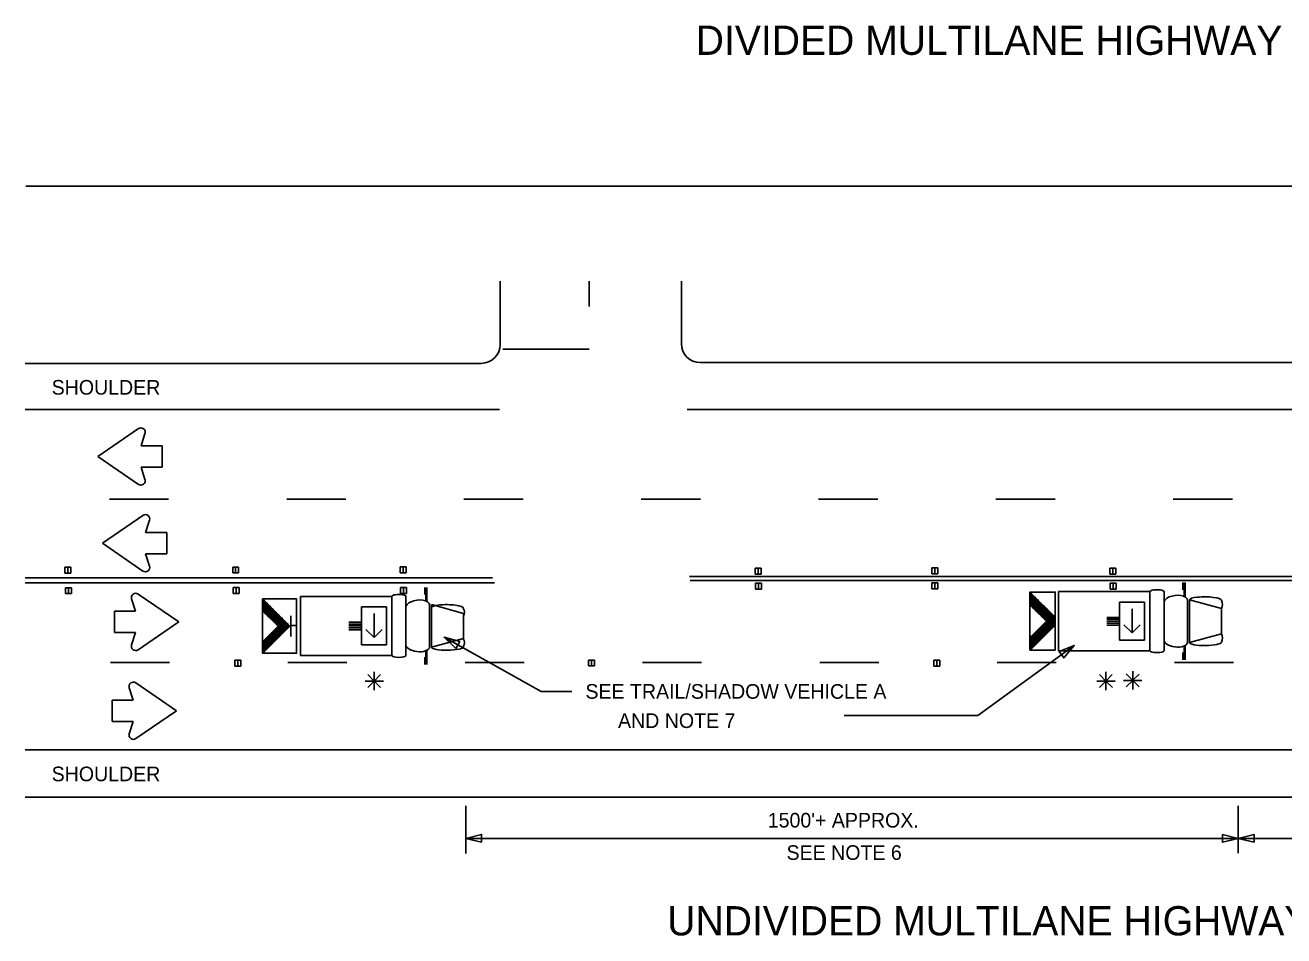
# Model space of a CAD drawing. Extents: x 1373848 to 1374003, y 380642 to 381248.
# Drawn here: x 1373848.1 to 1373899.8, y 380980.5 to 381017.9 of the extents above; entities that cross this region are included whole.
import ezdxf

# ---------------------------------------------------------------- set-up
doc = ezdxf.new("R2010")
doc.units = 0
doc.layers.add('Level 1', color=7, linetype='Continuous')
doc.layers.add('Working Level 1', color=7, linetype='Continuous')

msp = doc.modelspace()

# ---------------------------------------------------------------- linework, layer by layer
at = {"layer": 'Level 1'}
for points in [[(1373865.303, 380992.763), (1373869.287, 380990.533), (1373870.541, 380990.533)], [(1373891.159, 380992.429), (1373887.203, 380989.558), (1373881.714, 380989.558)]]:
    msp.add_lwpolyline(points, dxfattribs=at)
at = {"layer": 'Working Level 1'}
for p, q in [((1373848.144, 381011.273), (1373928.089, 381011.273)), ((1373867.608, 381004.776), (1373867.608, 381007.375)), ((1373875.04, 381004.805), (1373875.04, 381007.375)), ((1373867.714, 381004.589), (1373871.261, 381004.589)), ((1373848.118, 381004), (1373866.832, 381004)), ((1373875.816, 381004.029), (1373928.123, 381004.029)), ((1373848.118, 381002.105), (1373867.574, 381002.105)), ((1373875.274, 381002.105), (1373928.123, 381002.105)), ((1373851.099, 381000.18), (1373852.766, 381001.324)), ((1373852.871, 381000.616), (1373853.034, 381001.124)), ((1373851.099, 381000.18), (1373852.766, 380999.036)), ((1373853.738, 381000.616), (1373852.871, 381000.616)), ((1373853.738, 381000.616), (1373853.738, 380999.743)), ((1373853.738, 380999.743), (1373852.871, 380999.743)), ((1373852.871, 380999.743), (1373853.034, 380999.236)), ((1373851.285, 380996.622), (1373852.952, 380997.765)), ((1373853.057, 380997.058), (1373853.22, 380997.566)), ((1373851.285, 380996.622), (1373852.952, 380995.478)), ((1373853.925, 380997.058), (1373853.057, 380997.058)), ((1373853.925, 380997.058), (1373853.925, 380996.185)), ((1373853.925, 380996.185), (1373853.057, 380996.185)), ((1373853.057, 380996.185), (1373853.22, 380995.678)), ((1373849.752, 380995.633), (1373849.751, 380995.39)), ((1373849.994, 380995.633), (1373849.752, 380995.633)), ((1373849.873, 380995.633), (1373849.873, 380995.39)), ((1373849.994, 380995.39), (1373849.994, 380995.633)), ((1373856.875, 380995.644), (1373856.632, 380995.644)), ((1373856.632, 380995.644), (1373856.632, 380995.401)), ((1373856.754, 380995.644), (1373856.754, 380995.401)), ((1373856.875, 380995.401), (1373856.875, 380995.644)), ((1373863.507, 380995.656), (1373863.506, 380995.413)), ((1373863.749, 380995.656), (1373863.507, 380995.656)), ((1373863.628, 380995.656), (1373863.628, 380995.413)), ((1373863.749, 380995.413), (1373863.749, 380995.656)), ((1373878.314, 380995.591), (1373878.071, 380995.591)), ((1373878.071, 380995.591), (1373878.071, 380995.348)), ((1373878.193, 380995.591), (1373878.193, 380995.348)), ((1373878.314, 380995.348), (1373878.314, 380995.591)), ((1373885.558, 380995.609), (1373885.315, 380995.609)), ((1373885.315, 380995.609), (1373885.315, 380995.366)), ((1373885.437, 380995.609), (1373885.437, 380995.366)), ((1373885.558, 380995.366), (1373885.558, 380995.609)), ((1373892.625, 380995.601), (1373892.624, 380995.358)), ((1373892.867, 380995.601), (1373892.625, 380995.601)), ((1373892.746, 380995.601), (1373892.746, 380995.358)), ((1373892.867, 380995.358), (1373892.867, 380995.601)), ((1373848.118, 380995.204), (1373867.298, 380995.204)), ((1373849.751, 380995.39), (1373849.994, 380995.39)), ((1373856.632, 380995.401), (1373856.875, 380995.401)), ((1373863.506, 380995.413), (1373863.749, 380995.413)), ((1373875.372, 380995.257), (1373928.123, 380995.257)), ((1373875.406, 380995.089), (1373928.123, 380995.089)), ((1373878.071, 380995.348), (1373878.314, 380995.348)), ((1373885.315, 380995.366), (1373885.558, 380995.366)), ((1373892.624, 380995.358), (1373892.867, 380995.358)), ((1373895.619, 380994.707), (1373895.619, 380995.004)), ((1373895.666, 380994.422), (1373895.666, 380995.004)), ((1373895.706, 380994.422), (1373895.706, 380995.004)), ((1373848.118, 380994.992), (1373867.378, 380994.992)), ((1373850.015, 380994.797), (1373849.772, 380994.797)), ((1373849.772, 380994.797), (1373849.772, 380994.554)), ((1373849.772, 380994.554), (1373850.015, 380994.554)), ((1373849.894, 380994.797), (1373849.893, 380994.554)), ((1373850.015, 380994.554), (1373850.015, 380994.797)), ((1373854.418, 380993.394), (1373852.751, 380994.537)), ((1373856.653, 380994.808), (1373856.652, 380994.565)), ((1373856.652, 380994.565), (1373856.895, 380994.565)), ((1373856.895, 380994.808), (1373856.653, 380994.808)), ((1373856.774, 380994.808), (1373856.774, 380994.565)), ((1373856.895, 380994.565), (1373856.895, 380994.808)), ((1373863.515, 380994.808), (1373863.514, 380994.565)), ((1373863.514, 380994.565), (1373863.757, 380994.565)), ((1373863.757, 380994.808), (1373863.515, 380994.808)), ((1373863.636, 380994.808), (1373863.636, 380994.565)), ((1373863.757, 380994.565), (1373863.757, 380994.808)), ((1373864.515, 380994.514), (1373864.515, 380994.811)), ((1373864.562, 380994.229), (1373864.562, 380994.811)), ((1373864.601, 380994.229), (1373864.601, 380994.811)), ((1373878.325, 380994.98), (1373878.082, 380994.98)), ((1373878.082, 380994.98), (1373878.082, 380994.737)), ((1373878.082, 380994.737), (1373878.325, 380994.737)), ((1373878.204, 380994.98), (1373878.204, 380994.737)), ((1373878.325, 380994.737), (1373878.325, 380994.98)), ((1373885.561, 380994.991), (1373885.318, 380994.991)), ((1373885.318, 380994.991), (1373885.318, 380994.748)), ((1373885.318, 380994.748), (1373885.561, 380994.748)), ((1373885.44, 380994.991), (1373885.439, 380994.748)), ((1373885.561, 380994.748), (1373885.561, 380994.991)), ((1373889.343, 380994.617), (1373890.379, 380993.582)), ((1373890.514, 380994.635), (1373894.268, 380994.635)), ((1373890.514, 380992.209), (1373890.514, 380994.635)), ((1373892.878, 380994.984), (1373892.635, 380994.984)), ((1373892.635, 380994.984), (1373892.635, 380994.741)), ((1373892.635, 380994.741), (1373892.878, 380994.741)), ((1373892.757, 380994.984), (1373892.757, 380994.741)), ((1373892.878, 380994.741), (1373892.878, 380994.984)), ((1373894.268, 380993.422), (1373894.268, 380994.635)), ((1373894.844, 380993.422), (1373894.844, 380994.635)), ((1373852.646, 380993.83), (1373852.483, 380994.337)), ((1373857.861, 380994.338), (1373858.98, 380993.221)), ((1373859.409, 380994.442), (1373863.164, 380994.442)), ((1373859.409, 380992.016), (1373859.409, 380994.442)), ((1373862.944, 380994.005), (1373861.917, 380994.005)), ((1373861.917, 380992.453), (1373861.917, 380994.005)), ((1373862.944, 380994.005), (1373862.944, 380992.453)), ((1373863.164, 380993.229), (1373863.164, 380994.442)), ((1373863.739, 380993.229), (1373863.739, 380994.442)), ((1373864.703, 380993.229), (1373864.703, 380994.103)), ((1373864.783, 380994.103), (1373866.096, 380993.744)), ((1373864.783, 380993.229), (1373864.783, 380994.103)), ((1373889.343, 380994.099), (1373890.027, 380993.419)), ((1373894.048, 380994.198), (1373893.022, 380994.198)), ((1373893.022, 380992.646), (1373893.022, 380994.198)), ((1373894.048, 380994.198), (1373894.048, 380992.646)), ((1373895.807, 380993.422), (1373895.807, 380994.296)), ((1373895.887, 380994.296), (1373897.2, 380993.937)), ((1373895.887, 380993.422), (1373895.887, 380994.296)), ((1373851.778, 380992.957), (1373851.778, 380993.83)), ((1373851.778, 380993.83), (1373852.646, 380993.83)), ((1373857.861, 380993.853), (1373858.503, 380993.214)), ((1373859.017, 380992.8), (1373859.017, 380993.641)), ((1373862.431, 380993.742), (1373862.431, 380992.748)), ((1373866.096, 380993.229), (1373866.096, 380993.744)), ((1373893.022, 380993.577), (1373892.499, 380993.577)), ((1373893.022, 380993.499), (1373892.499, 380993.499)), ((1373893.535, 380993.935), (1373893.535, 380992.941)), ((1373897.2, 380993.422), (1373897.2, 380993.937)), ((1373851.778, 380992.957), (1373852.646, 380992.957)), ((1373852.646, 380992.957), (1373852.483, 380992.45)), ((1373854.418, 380993.394), (1373852.751, 380992.25)), ((1373857.861, 380992.575), (1373858.503, 380993.214)), ((1373857.868, 380992.108), (1373858.98, 380993.221)), ((1373859.251, 380993.241), (1373859.01, 380993.241)), ((1373861.917, 380993.384), (1373861.395, 380993.384)), ((1373861.917, 380993.306), (1373861.395, 380993.306)), ((1373861.917, 380993.229), (1373861.395, 380993.229)), ((1373861.917, 380993.151), (1373861.395, 380993.151)), ((1373861.917, 380993.073), (1373861.395, 380993.073)), ((1373862.431, 380992.748), (1373862.093, 380993.086)), ((1373862.431, 380992.748), (1373862.76, 380993.078)), ((1373863.164, 380993.229), (1373863.164, 380992.017)), ((1373863.739, 380993.229), (1373863.739, 380992.017)), ((1373864.703, 380993.229), (1373864.703, 380992.356)), ((1373864.783, 380993.229), (1373864.783, 380992.356)), ((1373866.096, 380993.229), (1373866.096, 380992.714)), ((1373889.343, 380992.736), (1373890.027, 380993.419)), ((1373889.35, 380992.239), (1373890.374, 380993.264)), ((1373893.022, 380993.422), (1373892.499, 380993.422)), ((1373893.022, 380993.344), (1373892.499, 380993.344)), ((1373893.022, 380993.266), (1373892.499, 380993.266)), ((1373893.535, 380992.941), (1373893.197, 380993.279)), ((1373893.535, 380992.941), (1373893.864, 380993.271)), ((1373894.268, 380993.422), (1373894.268, 380992.21)), ((1373894.844, 380993.422), (1373894.844, 380992.21)), ((1373895.807, 380993.422), (1373895.807, 380992.549)), ((1373895.887, 380993.422), (1373895.887, 380992.549)), ((1373897.2, 380993.422), (1373897.2, 380992.908)), ((1373862.944, 380992.453), (1373861.917, 380992.453)), ((1373864.783, 380992.356), (1373866.096, 380992.714)), ((1373894.048, 380992.646), (1373893.022, 380992.646)), ((1373895.666, 380992.423), (1373895.666, 380991.84)), ((1373895.706, 380992.423), (1373895.706, 380991.84)), ((1373895.887, 380992.549), (1373897.2, 380992.908)), ((1373859.409, 380992.017), (1373863.164, 380992.017)), ((1373864.515, 380991.944), (1373864.515, 380991.647)), ((1373864.562, 380992.229), (1373864.562, 380991.647)), ((1373864.601, 380992.229), (1373864.601, 380991.647)), ((1373890.514, 380992.21), (1373894.268, 380992.21)), ((1373895.619, 380992.137), (1373895.619, 380991.84)), ((1373856.963, 380991.818), (1373856.72, 380991.818)), ((1373856.72, 380991.818), (1373856.72, 380991.575)), ((1373856.72, 380991.575), (1373856.963, 380991.575)), ((1373856.842, 380991.818), (1373856.841, 380991.575)), ((1373856.963, 380991.575), (1373856.963, 380991.818)), ((1373871.236, 380991.829), (1373871.235, 380991.586)), ((1373871.235, 380991.586), (1373871.478, 380991.586)), ((1373871.478, 380991.829), (1373871.236, 380991.829)), ((1373871.357, 380991.829), (1373871.357, 380991.586)), ((1373871.478, 380991.586), (1373871.478, 380991.829)), ((1373885.643, 380991.818), (1373885.4, 380991.818)), ((1373885.4, 380991.818), (1373885.4, 380991.575)), ((1373885.4, 380991.575), (1373885.643, 380991.575)), ((1373885.522, 380991.818), (1373885.521, 380991.575)), ((1373885.643, 380991.575), (1373885.643, 380991.818)), ((1373854.326, 380989.748), (1373852.659, 380990.892)), ((1373862.437, 380990.968), (1373862.061, 380990.968)), ((1373862.437, 380990.968), (1373862.171, 380991.234)), ((1373862.437, 380990.968), (1373862.171, 380990.702)), ((1373862.431, 380990.963), (1373862.697, 380991.229)), ((1373862.437, 380990.968), (1373862.437, 380991.344)), ((1373862.437, 380990.968), (1373862.703, 380990.702)), ((1373862.437, 380990.968), (1373862.437, 380990.592)), ((1373862.437, 380990.968), (1373862.813, 380990.968)), ((1373892.462, 380990.968), (1373892.086, 380990.968)), ((1373892.462, 380990.968), (1373892.196, 380991.234)), ((1373892.462, 380990.968), (1373892.196, 380990.702)), ((1373892.456, 380990.963), (1373892.722, 380991.229)), ((1373892.462, 380990.968), (1373892.462, 380991.344)), ((1373892.462, 380990.968), (1373892.728, 380990.702)), ((1373892.462, 380990.968), (1373892.462, 380990.592)), ((1373892.462, 380990.968), (1373892.838, 380990.968)), ((1373893.56, 380990.992), (1373893.184, 380990.992)), ((1373893.56, 380990.992), (1373893.294, 380991.258)), ((1373893.56, 380990.992), (1373893.294, 380990.726)), ((1373893.554, 380990.987), (1373893.82, 380991.253)), ((1373893.56, 380990.992), (1373893.56, 380991.368)), ((1373893.56, 380990.992), (1373893.826, 380990.726)), ((1373893.56, 380990.992), (1373893.56, 380990.616)), ((1373893.56, 380990.992), (1373893.936, 380990.992)), ((1373852.553, 380990.185), (1373852.39, 380990.692)), ((1373851.686, 380989.312), (1373851.686, 380990.185)), ((1373851.686, 380990.185), (1373852.553, 380990.185)), ((1373854.326, 380989.748), (1373852.659, 380988.605)), ((1373851.686, 380989.312), (1373852.553, 380989.312)), ((1373852.553, 380989.312), (1373852.39, 380988.805)), ((1373848.118, 380988.139), (1373928.123, 380988.139)), ((1373848.118, 380986.201), (1373928.123, 380986.201)), ((1373866.195, 380985.853), (1373866.195, 380983.887)), ((1373897.891, 380985.853), (1373897.891, 380983.906)), ((1373866.195, 380984.513), (1373897.891, 380984.513)), ((1373866.195, 380984.513), (1373866.738, 380984.513)), ((1373897.891, 380984.513), (1373897.619, 380984.513)), ((1373897.891, 380984.513), (1373898.443, 380984.513)), ((1373897.891, 380984.513), (1373907.836, 380984.513))]:
    msp.add_line(p, q, dxfattribs=at)
for points in [[(1373871.257, 381007.375), (1373871.257, 381006.328)], [(1373851.571, 380998.431), (1373853.997, 380998.431)], [(1373858.847, 380998.431), (1373861.272, 380998.431)], [(1373866.122, 380998.431), (1373868.548, 380998.431)], [(1373873.398, 380998.431), (1373875.823, 380998.431)], [(1373880.673, 380998.431), (1373883.099, 380998.431)], [(1373887.949, 380998.431), (1373890.374, 380998.431)], [(1373895.224, 380998.431), (1373897.65, 380998.431)], [(1373889.343, 380994.561), (1373889.972, 380993.472)], [(1373889.396, 380994.564), (1373890.229, 380993.12)], [(1373857.861, 380994.285), (1373858.452, 380993.264)], [(1373857.861, 380994.198), (1373858.335, 380993.378)], [(1373857.861, 380994.11), (1373858.218, 380993.492)], [(1373857.861, 380994.022), (1373858.101, 380993.607)], [(1373857.911, 380994.289), (1373858.692, 380992.935)], [(1373858.031, 380994.169), (1373858.725, 380992.967)], [(1373858.15, 380994.049), (1373858.757, 380992.999)], [(1373889.343, 380994.468), (1373889.848, 380993.593)], [(1373889.343, 380994.374), (1373889.723, 380993.715)], [(1373889.343, 380994.28), (1373889.599, 380993.837)], [(1373889.343, 380994.186), (1373889.474, 380993.959)], [(1373889.343, 380994.092), (1373889.35, 380994.082)], [(1373889.524, 380994.436), (1373890.264, 380993.154)], [(1373889.652, 380994.309), (1373890.298, 380993.189)], [(1373889.78, 380994.181), (1373890.333, 380993.223)], [(1373889.907, 380994.053), (1373890.367, 380993.257)], [(1373857.861, 380993.934), (1373857.985, 380993.722)], [(1373857.861, 380993.846), (1373857.868, 380993.836)], [(1373858.271, 380993.929), (1373858.789, 380993.031)], [(1373858.39, 380993.809), (1373858.821, 380993.063)], [(1373858.51, 380993.689), (1373858.855, 380993.093)], [(1373858.63, 380993.57), (1373858.888, 380993.124)], [(1373858.75, 380993.451), (1373858.917, 380993.161)], [(1373890.035, 380993.925), (1373890.375, 380993.337)], [(1373890.163, 380993.797), (1373890.377, 380993.428)], [(1373890.291, 380993.67), (1373890.378, 380993.519)], [(1373858.23, 380992.943), (1373858.402, 380992.646)], [(1373858.263, 380992.976), (1373858.435, 380992.678)], [(1373858.295, 380993.008), (1373858.467, 380992.711)], [(1373858.327, 380993.039), (1373858.499, 380992.742)], [(1373858.359, 380993.072), (1373858.532, 380992.774)], [(1373858.391, 380993.104), (1373858.564, 380992.807)], [(1373858.424, 380993.136), (1373858.596, 380992.838)], [(1373858.455, 380993.169), (1373858.629, 380992.871)], [(1373858.488, 380993.201), (1373858.661, 380992.903)], [(1373858.861, 380993.342), (1373858.947, 380993.192)], [(1373889.565, 380992.958), (1373889.748, 380992.641)], [(1373889.6, 380992.992), (1373889.783, 380992.676)], [(1373889.634, 380993.027), (1373889.817, 380992.71)], [(1373889.668, 380993.061), (1373889.851, 380992.744)], [(1373889.703, 380993.096), (1373889.886, 380992.778)], [(1373889.737, 380993.13), (1373889.92, 380992.812)], [(1373889.771, 380993.164), (1373889.955, 380992.846)], [(1373889.805, 380993.199), (1373889.989, 380992.881)], [(1373889.84, 380993.232), (1373890.023, 380992.915)], [(1373889.874, 380993.267), (1373890.058, 380992.949)], [(1373889.908, 380993.301), (1373890.092, 380992.984)], [(1373889.943, 380993.335), (1373890.126, 380993.018)], [(1373889.977, 380993.37), (1373890.161, 380993.052)], [(1373890.012, 380993.404), (1373890.195, 380993.086)], [(1373857.861, 380992.528), (1373858.016, 380992.261)], [(1373857.861, 380992.439), (1373857.983, 380992.229)], [(1373857.876, 380992.59), (1373858.048, 380992.294)], [(1373857.909, 380992.622), (1373858.08, 380992.325)], [(1373857.941, 380992.654), (1373858.112, 380992.358)], [(1373857.973, 380992.687), (1373858.145, 380992.389)], [(1373858.005, 380992.718), (1373858.177, 380992.422)], [(1373858.037, 380992.75), (1373858.209, 380992.454)], [(1373858.069, 380992.782), (1373858.241, 380992.486)], [(1373858.102, 380992.815), (1373858.274, 380992.518)], [(1373858.134, 380992.847), (1373858.306, 380992.55)], [(1373858.166, 380992.879), (1373858.338, 380992.582)], [(1373858.198, 380992.912), (1373858.37, 380992.614)], [(1373889.343, 380992.686), (1373889.508, 380992.402)], [(1373889.343, 380992.592), (1373889.473, 380992.368)], [(1373889.343, 380992.498), (1373889.439, 380992.333)], [(1373889.359, 380992.752), (1373889.542, 380992.437)], [(1373889.394, 380992.787), (1373889.576, 380992.47)], [(1373889.428, 380992.821), (1373889.61, 380992.505)], [(1373889.463, 380992.856), (1373889.645, 380992.538)], [(1373889.496, 380992.89), (1373889.679, 380992.573)], [(1373889.531, 380992.924), (1373889.714, 380992.607)], [(1373857.861, 380992.352), (1373857.951, 380992.197)], [(1373857.861, 380992.263), (1373857.919, 380992.165)], [(1373857.861, 380992.176), (1373857.886, 380992.133)], [(1373889.343, 380992.405), (1373889.404, 380992.299)], [(1373889.343, 380992.311), (1373889.37, 380992.265)], [(1373851.615, 380991.733), (1373854.041, 380991.733)], [(1373858.891, 380991.733), (1373861.316, 380991.733)], [(1373866.166, 380991.733), (1373868.592, 380991.733)], [(1373873.442, 380991.733), (1373875.867, 380991.733)], [(1373880.717, 380991.733), (1373883.142, 380991.733)], [(1373887.992, 380991.733), (1373890.418, 380991.733)], [(1373895.268, 380991.733), (1373897.693, 380991.733)]]:
    msp.add_lwpolyline(points, dxfattribs=at)
for points in [[(1373890.382, 380992.239), (1373889.343, 380992.239), (1373889.343, 380994.617), (1373890.382, 380994.617)], [(1373857.861, 380994.338), (1373857.861, 380992.108), (1373859.255, 380992.108), (1373859.255, 380994.338)], [(1373865.79, 380992.304), (1373865.303, 380992.763), (1373865.949, 380992.588)], [(1373890.538, 380992.179), (1373891.159, 380992.429), (1373890.729, 380991.916)], [(1373866.845, 380984.35), (1373866.195, 380984.513), (1373866.845, 380984.675)], [(1373897.241, 380984.675), (1373897.891, 380984.513), (1373897.241, 380984.35)], [(1373898.541, 380984.35), (1373897.891, 380984.513), (1373898.541, 380984.675)]]:
    msp.add_lwpolyline(points, close=True, dxfattribs=at)
for centre, radius, start, end in [((1373866.832, 381004.776), 0.776, 270, 360), ((1373875.816, 381004.805), 0.776, 180, 270), ((1373852.866, 381001.178), 0.177, 342.1824, 124.4455), ((1373852.866, 380999.182), 0.177, 235.5545, 17.8176), ((1373853.052, 380997.619), 0.177, 342.1824, 124.4455), ((1373853.052, 380995.624), 0.177, 235.5545, 17.8176), ((1373852.652, 380994.391), 0.177, 55.5545, 197.8176), ((1373896.879, 380994.108), 0.364, 331.8801, 28.1199), ((1373865.774, 380993.788), 0.364, 331.8801, 28.1199), ((1373852.652, 380992.396), 0.177, 162.1824, 304.4455), ((1373865.774, 380992.543), 0.364, 331.8801, 28.1199), ((1373896.879, 380992.736), 0.364, 331.8801, 28.1199), ((1373852.559, 380990.746), 0.177, 55.5545, 197.8176), ((1373852.559, 380988.751), 0.177, 162.1824, 304.4455)]:
    msp.add_arc(centre, radius, start, end, dxfattribs=at)
for centre, major_axis, ratio, start_param, end_param in [((1373863.452, 380994.442), (0.288, 0), 0.269913, 0, 3.141593), ((1373894.556, 380994.635), (0.288, 0), 0.269913, 0, 3.141593), ((1373895.325, 380994.236), (0.482, 0.06), 0.503092, 0, 3.141593), ((1373864.221, 380994.043), (0.482, 0.06), 0.503092, 0, 3.141593), ((1373865.439, 380993.968), (0.656, -0.008), 0.2034, 0, 3.141593), ((1373896.544, 380994.288), (0.656, -0.008), 0.2034, 0, 3.141593), ((1373864.221, 380992.415), (0.482, -0.06), 0.503092, 3.141593, 6.283185), ((1373895.325, 380992.608), (0.482, -0.06), 0.503092, 3.141593, 6.283185), ((1373896.544, 380992.556), (0.656, 0.008), 0.2034, 3.141593, 6.283185), ((1373863.452, 380992.017), (0.288, 0), 0.269913, 3.141593, 6.283185), ((1373865.439, 380992.363), (0.656, 0.008), 0.2034, 3.141593, 6.283185), ((1373894.556, 380992.21), (0.288, 0), 0.269913, 3.141593, 6.283185)]:
    msp.add_ellipse(centre, major_axis=major_axis, ratio=ratio, start_param=start_param, end_param=end_param, dxfattribs=at)

# ---------------------------------------------------------------- texts
for s, height, p in [('DIVIDED MULTILANE HIGHWAY', 1.2, (1373875.629, 381016.657)), ('SHOULDER', 0.6, (1373849.205, 381002.717)), ('SHOULDER', 0.6, (1373849.205, 380986.856)), ('UNDIVIDED MULTILANE HIGHWAY', 1.2, (1373874.46, 380980.531))]:
    msp.add_text(s, height=height, rotation=0, dxfattribs=at).set_placement(p)
for s, p in [('SEE TRAIL/SHADOW VEHICLE A', (1373871.105, 380990.241)), ('      AND NOTE 7', (1373871.105, 380989.041)), ("1500'+ APPROX.", (1373878.585, 380984.958)), ('SEE NOTE 6', (1373879.357, 380983.63))]:
    msp.add_text(s, height=0.6, dxfattribs=at).set_placement(p)

doc.saveas('drawing.dxf')
